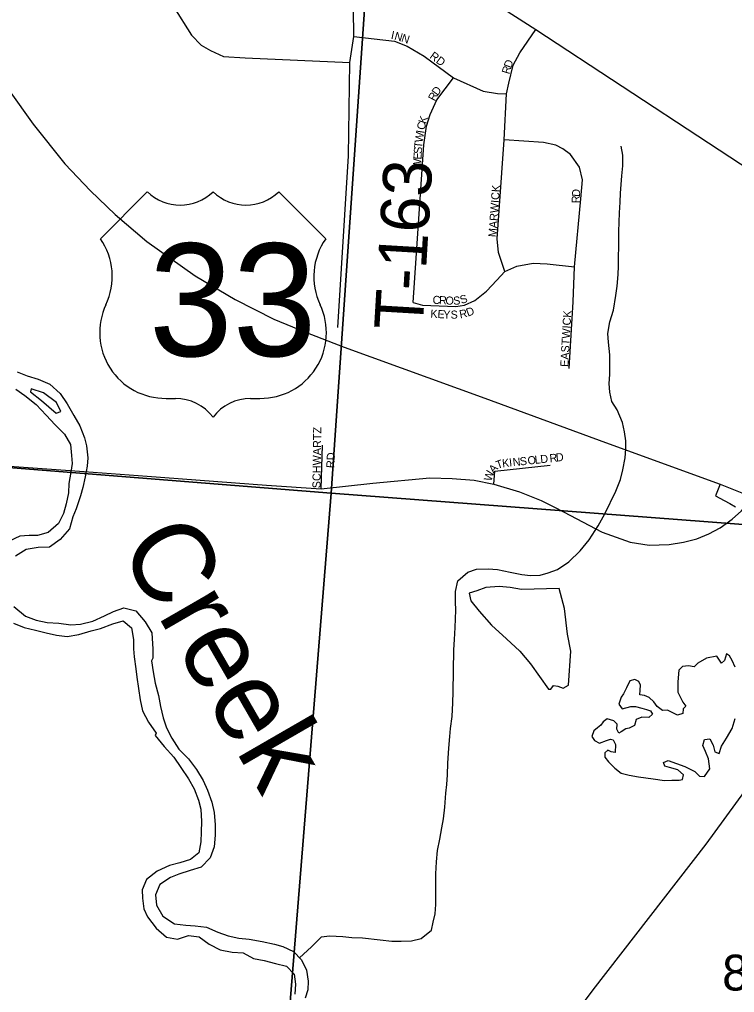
# Model space of a CAD drawing. Extents: x 0 to 34, y 0 to 22.
# Drawn here: x 4.758 to 5.595, y 16.625 to 17.763 of the extents above; entities that cross this region are included whole.
import ezdxf

# ---------------------------------------------------------------- set-up
doc = ezdxf.new("R2010")
doc.units = 0
for name, color, linetype in [('GM_X_City_Street', 7, 'Continuous'), ('GM_X_City_Street_Text', 7, 'Continuous'), ('GM_X_County_Road', 7, 'Continuous'), ('GM_X_Interchange_Ramps', 7, 'Continuous'), ('GM_X_Interstate_Route', 7, 'Continuous'), ('GM_X_Major_River', 7, 'Continuous'), ('GM_X_Major_River_Text', 7, 'Continuous'), ('GM_X_Minor_Lake', 7, 'Continuous'), ('GM_X_Minor_River', 7, 'Continuous'), ('GM_X_Section', 7, 'Continuous'), ('GM_X_Section_Text', 7, 'Continuous'), ('GM_X_Township_Road', 7, 'Continuous'), ('GM_X_Township_Road_Text', 7, 'Continuous'), ('GM_X_Township_Subdivision', 7, 'Continuous'), ('GM_X_Township_Subdivision_Text', 7, 'Continuous'), ('GM_X_US_Location', 7, 'Continuous'), ('GM_X_US_Route', 7, 'Continuous'), ('GM_X_US_Shield', 7, 'Continuous')]:
    doc.layers.add(name, color=color, linetype=linetype)

msp = doc.modelspace()

# ---------------------------------------------------------------- linework, layer by layer
at = {"layer": 'GM_X_City_Street'}
for points in [[(4.8031, 17.8552), (4.8596, 17.8527), (4.8838, 17.8507), (4.8933, 17.8454), (4.906, 17.8276), (4.9148, 17.8153), (4.9389, 17.7773), (4.9593, 17.7446), (4.9706, 17.7328), (4.9816, 17.7267), (4.9967, 17.7194), (5.0224, 17.7178), (5.1448, 17.7126)], [(5.1112, 17.2137), (5.1127, 17.2649)], [(4.5988, 17.2527), (4.5987, 17.2509), (4.8338, 17.234), (4.9075, 17.2287), (5.0472, 17.218), (5.1112, 17.2137), (5.1718, 17.2206), (5.2384, 17.2265), (5.2646, 17.2259), (5.2903, 17.2238), (5.3134, 17.2192), (5.3431, 17.2104), (5.3688, 17.2001), (5.3842, 17.1924), (5.3949, 17.1868), (5.44, 17.1631), (5.4728, 17.1515), (5.4951, 17.1479), (5.5183, 17.1487), (5.5352, 17.1515), (5.5507, 17.1555), (5.565, 17.1611), (5.578, 17.1683), (5.5851, 17.1734)], [(5.3134, 17.2192), (5.3146, 17.2344), (5.3792, 17.2413)], [(5.5851, 17.1734), (5.5923, 17.1785), (5.603, 17.1882), (5.6115, 17.1981), (5.6165, 17.2048), (5.6259, 17.2193), (5.6277, 17.2232), (5.6289, 17.226)]]:
    msp.add_lwpolyline(points, dxfattribs=at)
at = {"layer": 'GM_X_County_Road'}
msp.add_lwpolyline([(5.1496, 17.8918), (5.1573, 17.8838), (5.1678, 17.876), (5.3625, 17.7509), (5.6653, 17.5523), (5.7694, 17.4837), (5.8147, 17.4543), (5.8758, 17.4145), (5.8966, 17.4004), (5.9787, 17.3454), (5.9879, 17.3394), (6.1472, 17.2345), (6.3013, 17.1331), (6.3963, 17.0731), (6.4389, 17.0483), (6.4571, 17.0376), (6.4744, 17.0295), (6.5397, 17.0026), (6.5904, 16.9823)], dxfattribs=at)
at = {"layer": 'GM_X_Interchange_Ramps'}
msp.add_lwpolyline([(5.578, 17.2191), (5.5726, 17.2058), (5.5828, 17.2003), (5.5894, 17.1965), (5.596, 17.1926)], dxfattribs=at)
at = {"layer": 'GM_X_Interstate_Route'}
msp.add_lwpolyline([(5.6064, 16.86), (5.5612, 16.7983), (5.4292, 16.6277), (5.3235, 16.4867), (5.1841, 16.3077), (5.0901, 16.1822)], dxfattribs=at)
at = {"layer": 'GM_X_Major_River'}
for points in [[(4.7554, 17.3506), (4.7671, 17.346), (4.78, 17.3419), (4.7936, 17.3362), (4.8057, 17.3252), (4.8141, 17.3134), (4.8216, 17.2994), (4.8288, 17.2873), (4.8341, 17.2736), (4.8364, 17.2641), (4.8383, 17.2501), (4.8375, 17.2403), (4.8352, 17.2277), (4.8322, 17.2152), (4.8296, 17.2057), (4.8243, 17.1906), (4.8205, 17.1811), (4.8167, 17.167), (4.8057, 17.1545), (4.7932, 17.1454), (4.7799, 17.145), (4.7659, 17.1428), (4.7534, 17.1352)], [(4.7539, 17.3305), (4.7645, 17.3229), (4.7777, 17.3123), (4.7894, 17.2998), (4.8, 17.2888), (4.811, 17.2778), (4.8178, 17.2657), (4.819, 17.2528), (4.8197, 17.2433), (4.8182, 17.2334), (4.8159, 17.2201), (4.8155, 17.2091), (4.8129, 17.1962), (4.8095, 17.1849), (4.8038, 17.1731), (4.7917, 17.1629), (4.7792, 17.1594), (4.7693, 17.1594), (4.7587, 17.1583), (4.7462, 17.1526)], [(4.8065, 17.3043), (4.8016, 17.3146), (4.7864, 17.3259), (4.772, 17.3309), (4.7709, 17.3271)], [(4.7709, 17.3271), (4.7841, 17.3172), (4.8012, 17.3024), (4.8065, 17.3043)], [(4.7515, 17.076), (4.7652, 17.065), (4.7777, 17.0601), (4.7905, 17.0574), (4.8042, 17.0567), (4.8182, 17.0548), (4.8295, 17.0556), (4.8439, 17.059), (4.8575, 17.0654), (4.8682, 17.0704), (4.8803, 17.0745), (4.8943, 17.0711), (4.9053, 17.0583), (4.9132, 17.0454), (4.914, 17.0264), (4.914, 17.0158)], [(4.7511, 17.0567), (4.7636, 17.0517), (4.7769, 17.0483), (4.7894, 17.0453), (4.8015, 17.0427), (4.814, 17.0411), (4.8276, 17.0434), (4.842, 17.0476), (4.853, 17.0506), (4.8674, 17.056), (4.8795, 17.0594), (4.8894, 17.0514), (4.8916, 17.0374), (4.8916, 17.0268), (4.8924, 17.0173), (4.8943, 17.0033), (4.8954, 16.9934), (4.8992, 16.9669), (4.9022, 16.954), (4.909, 16.9407), (4.9181, 16.9282)], [(4.914, 17.0158), (4.9128, 17.0128), (4.9147, 16.9999), (4.917, 16.9866), (4.9208, 16.9722), (4.923, 16.9593), (4.9264, 16.946), (4.9302, 16.9343), (4.9363, 16.9221), (4.9446, 16.9092), (4.956, 16.8979), (4.9654, 16.8854), (4.973, 16.8725), (4.9783, 16.8615), (4.9832, 16.8474), (4.9859, 16.8353), (4.987, 16.8209), (4.987, 16.8088), (4.9859, 16.7951), (4.9813, 16.7822), (4.9707, 16.7712), (4.9578, 16.7674), (4.9446, 16.7632), (4.9347, 16.7591), (4.9222, 16.7511), (4.9173, 16.7389), (4.9184, 16.7268), (4.926, 16.7139), (4.9396, 16.7048), (4.9529, 16.7033), (4.9639, 16.7026), (4.9771, 16.7011), (4.9904, 16.6954), (5.0025, 16.6908), (5.015, 16.6882), (5.0271, 16.6871), (5.0423, 16.6844), (5.0566, 16.6814), (5.0665, 16.6784), (5.079, 16.6727), (5.0881, 16.6628), (5.0941, 16.6507), (5.096, 16.6378), (5.0956, 16.6276), (5.0926, 16.6181)], [(4.9181, 16.9282), (4.917, 16.9252), (4.9276, 16.9123), (4.9389, 16.9001), (4.9469, 16.888), (4.956, 16.8747), (4.9624, 16.863), (4.9677, 16.8497), (4.9703, 16.8391), (4.9711, 16.8247), (4.9707, 16.8125), (4.9703, 16.8008), (4.9681, 16.7879), (4.9582, 16.7803), (4.9457, 16.7765), (4.9336, 16.7731), (4.9192, 16.7666), (4.9067, 16.7568), (4.9018, 16.7446), (4.9022, 16.7351), (4.9037, 16.7226), (4.9078, 16.7132), (4.9181, 16.6999), (4.9302, 16.6893), (4.943, 16.687), (4.9559, 16.6912), (4.9684, 16.6897), (4.9802, 16.6813), (4.993, 16.6745), (5.007, 16.6719), (5.0199, 16.6711), (5.032, 16.6643), (5.0445, 16.662), (5.0578, 16.6586), (5.0706, 16.6556), (5.0794, 16.6461), (5.0812, 16.6344), (5.0805, 16.6226)]]:
    msp.add_lwpolyline(points, dxfattribs=at)
at = {"layer": 'GM_X_Minor_Lake'}
for points in [[(5.3771, 16.9793), (5.3798, 16.9793), (5.3829, 16.9838), (5.3882, 16.983), (5.3942, 16.9807), (5.4007, 16.9841), (5.4033, 17.0239), (5.3993, 17.044), (5.3958, 17.0737), (5.3896, 17.0972), (5.3457, 17.0961), (5.3325, 17.0985), (5.3196, 17.0997), (5.3037, 17.0983), (5.2934, 17.0946), (5.2843, 17.0916), (5.2865, 17.0829), (5.2959, 17.0707), (5.3105, 17.0542), (5.3281, 17.0382), (5.3435, 17.024), (5.3562, 17.0091)], [(5.5955, 17.0052), (5.5922, 17.0132), (5.5892, 17.0186), (5.5854, 17.0209), (5.5831, 17.0129), (5.5796, 17.0099), (5.5744, 17.0179), (5.5623, 17.0158), (5.552, 17.0098), (5.5478, 17.0056), (5.541, 17.0068), (5.5342, 17.0061), (5.5296, 17.0016), (5.5287, 16.988), (5.5286, 16.9758), (5.5345, 16.9644), (5.5379, 16.9594), (5.5348, 16.9564), (5.5344, 16.9511), (5.5283, 16.9489), (5.5166, 16.955), (5.5106, 16.9547), (5.5042, 16.9593), (5.5004, 16.9647), (5.4952, 16.9696), (5.4895, 16.972), (5.4842, 16.9728), (5.4843, 16.9785), (5.4847, 16.9841), (5.4829, 16.9883), (5.4784, 16.9906), (5.4723, 16.9892), (5.4684, 16.9809), (5.4649, 16.9741), (5.4623, 16.9703), (5.4595, 16.962), (5.4633, 16.9566), (5.4735, 16.9592), (5.4792, 16.9591), (5.4864, 16.9572), (5.492, 16.9556), (5.4966, 16.9541), (5.4988, 16.9503), (5.4946, 16.9465), (5.4866, 16.9469), (5.4798, 16.944), (5.4778, 16.9368), (5.4718, 16.9338), (5.4676, 16.9331), (5.4622, 16.9297), (5.4596, 16.9282), (5.457, 16.9328), (5.4574, 16.9385), (5.4537, 16.9423), (5.4499, 16.9438), (5.4457, 16.9446), (5.4412, 16.9412), (5.4385, 16.9375), (5.4346, 16.9341), (5.4301, 16.9307), (5.4281, 16.9243), (5.4311, 16.9193)], [(5.3562, 17.0091), (5.3771, 16.9793)], [(5.455, 16.8872), (5.4622, 16.8811), (5.4716, 16.8788), (5.4826, 16.8768), (5.4996, 16.8747), (5.5128, 16.8727), (5.5215, 16.873), (5.5302, 16.873), (5.534, 16.8737), (5.5352, 16.8794), (5.5285, 16.8851), (5.519, 16.8879), (5.5134, 16.8894), (5.5119, 16.8936), (5.5172, 16.8962), (5.5368, 16.8892), (5.5485, 16.8831), (5.5538, 16.8777), (5.5598, 16.8773), (5.566, 16.8863), (5.5646, 16.8981), (5.5609, 16.9065), (5.5579, 16.9137), (5.5598, 16.9205), (5.5659, 16.9212), (5.57, 16.914), (5.5718, 16.906), (5.5771, 16.9041), (5.5795, 16.9128), (5.5856, 16.9222), (5.5922, 16.9336), (5.5957, 16.9453)], [(5.4311, 16.9193), (5.4368, 16.9162), (5.4451, 16.9196), (5.4497, 16.9211), (5.4527, 16.9203), (5.4557, 16.9149), (5.4552, 16.9055), (5.4507, 16.9063), (5.4465, 16.9082), (5.4431, 16.9052), (5.443, 16.8999), (5.4476, 16.8944)], [(5.4476, 16.8944), (5.455, 16.8872)]]:
    msp.add_lwpolyline(points, dxfattribs=at)
at = {"layer": 'GM_X_Minor_River'}
msp.add_lwpolyline([(5.086, 16.6651), (5.0998, 16.678), (5.1116, 16.6897), (5.1211, 16.6911), (5.1366, 16.6902), (5.1472, 16.689), (5.1597, 16.6885), (5.1801, 16.6861), (5.1937, 16.6848), (5.2047, 16.6848), (5.2168, 16.685), (5.2282, 16.688), (5.2404, 16.6974), (5.2424, 16.7068), (5.2444, 16.7167), (5.2453, 16.7277), (5.2455, 16.752), (5.2452, 16.7634), (5.2461, 16.7774), (5.2474, 16.7907), (5.2502, 16.8039), (5.2525, 16.8172), (5.2545, 16.8278), (5.2558, 16.8414), (5.2571, 16.8577), (5.2583, 16.868), (5.2592, 16.8794), (5.2593, 16.893), (5.2606, 16.9105), (5.2619, 16.9241), (5.2627, 16.9336), (5.2644, 16.9476), (5.2653, 16.9635), (5.2658, 16.9764), (5.2663, 17.0254), (5.2671, 17.0375), (5.268, 17.0516), (5.2685, 17.0618), (5.2686, 17.0717), (5.2683, 17.0815), (5.2684, 17.0937), (5.2712, 17.1062), (5.2827, 17.1163), (5.2929, 17.1197), (5.3065, 17.1203), (5.3175, 17.1195), (5.3323, 17.1163), (5.3462, 17.1135), (5.3561, 17.1123), (5.3674, 17.113), (5.3769, 17.1156), (5.3879, 17.1196), (5.4009, 17.1283), (5.4143, 17.1414), (5.425, 17.1542), (5.4354, 17.1705), (5.4431, 17.1845), (5.4562, 17.2109), (5.4616, 17.2249), (5.4644, 17.2359), (5.4668, 17.2499), (5.4677, 17.2605), (5.4678, 17.27), (5.4663, 17.2806), (5.4638, 17.2913), (5.4575, 17.3061), (5.4515, 17.3161), (5.449, 17.3267), (5.4483, 17.337), (5.4488, 17.3476), (5.449, 17.3707), (5.4476, 17.3855), (5.4466, 17.3954), (5.449, 17.409), (5.4533, 17.4227), (5.4561, 17.4401), (5.4577, 17.4507), (5.4586, 17.4644), (5.4591, 17.4742), (5.4592, 17.4852), (5.4597, 17.497), (5.4595, 17.5148), (5.46, 17.5258), (5.4604, 17.5368), (5.4609, 17.549), (5.4614, 17.5596), (5.4631, 17.5801), (5.4644, 17.5918), (5.4641, 17.604), (5.4623, 17.6146)], dxfattribs=at)
at = {"layer": 'GM_X_Section'}
for points in [[(4.2418, 18.2267), (4.7469, 18.1907), (5.1885, 18.1592), (5.123, 17.2087), (4.1767, 17.2841)], [(5.1885, 18.1592), (5.2507, 18.1559), (5.7484, 18.1169), (6.2087, 18.0808), (6.1439, 17.131), (5.123, 17.2087)], [(4.1767, 17.2841), (5.123, 17.2087), (5.0408, 16.1927), (4.1066, 16.2613), (4.1718, 17.2163)], [(5.123, 17.2087), (6.1439, 17.131), (6.0779, 16.1089), (5.0408, 16.1927)]]:
    msp.add_lwpolyline(points, close=True, dxfattribs=at)
at = {"layer": 'GM_X_Township_Road'}
msp.add_lwpolyline([(5.1307, 17.4024), (5.1431, 17.6035), (5.1448, 17.7126), (5.1493, 17.7429), (5.149, 17.7754), (5.16, 17.8569), (5.1604, 17.8633), (5.1609, 17.8655), (5.1617, 17.8686), (5.1678, 17.876)], dxfattribs=at)
at = {"layer": 'GM_X_Township_Subdivision'}
for points in [[(5.326, 17.4681), (5.3188, 17.4901), (5.3172, 17.5063), (5.3254, 17.6222), (5.3282, 17.6757), (5.3307, 17.6884), (5.336, 17.7092), (5.3438, 17.7239), (5.3625, 17.7509)], [(5.1493, 17.7429), (5.197, 17.7376), (5.2118, 17.7315), (5.2318, 17.7198), (5.2659, 17.6944), (5.3007, 17.6789), (5.3177, 17.6763), (5.3282, 17.6757)], [(5.219, 17.4318), (5.2314, 17.6161), (5.2345, 17.638), (5.2386, 17.6517), (5.2466, 17.6687), (5.2659, 17.6944)], [(5.4013, 17.3546), (5.4062, 17.4325), (5.4077, 17.4734), (5.4152, 17.5532), (5.4172, 17.5753), (5.4136, 17.59), (5.4029, 17.6047), (5.394, 17.6116), (5.3858, 17.6157), (5.3715, 17.619), (5.3254, 17.6222)], [(5.219, 17.4318), (5.2299, 17.4287), (5.2689, 17.4272), (5.2791, 17.4287), (5.2912, 17.434), (5.3045, 17.445), (5.3166, 17.4579), (5.326, 17.4681), (5.34, 17.4742), (5.3593, 17.4779), (5.3756, 17.4768), (5.4077, 17.4734)]]:
    msp.add_lwpolyline(points, dxfattribs=at)
at = {"layer": 'GM_X_US_Route'}
msp.add_lwpolyline([(4.6943, 17.7748), (4.7113, 17.7399), (4.7276, 17.7105), (4.7461, 17.6796), (4.7741, 17.6405), (4.8111, 17.5941), (4.8412, 17.5624), (4.8703, 17.5346), (4.9071, 17.5032), (4.9636, 17.4629), (5.0105, 17.4353), (5.0559, 17.4124), (5.093, 17.397), (5.1381, 17.3797), (5.3028, 17.3197), (5.444, 17.2679), (5.578, 17.2191), (5.6056, 17.2084)], dxfattribs=at)
at = {"layer": 'GM_X_US_Shield'}
for p, q in [((4.9077, 17.5613), (4.8528, 17.5063)), ((5.1165, 17.5063), (5.0616, 17.5613)), ((4.9297, 17.3196), (4.9407, 17.3196)), ((5.0286, 17.3196), (5.0396, 17.3196))]:
    msp.add_line(p, q, dxfattribs=at)
for centre, radius, start, end in [((4.9462, 17.6005), 0.0549, 225.573, 314.427), ((5.0231, 17.6005), 0.0549, 225.573, 314.427), ((4.7898, 17.4622), 0.0769, 334.5471, 35.0009), ((5.1795, 17.4622), 0.0769, 144.9991, 205.4529), ((4.9289, 17.3965), 0.0769, 154.8319, 270.6383), ((5.0404, 17.3965), 0.0769, 269.3617, 25.1681), ((4.9407, 17.2646), 0.0549, 36.8699, 90), ((5.0286, 17.2646), 0.0549, 90, 143.1301)]:
    msp.add_arc(centre, radius, start, end, dxfattribs=at)

# ---------------------------------------------------------------- texts
at = {"layer": 'GM_X_City_Street_Text'}
for s, rotation, p in [('SCHWARTZ', 89.2466, (5.1104, 17.2144)), ('RD', 86.989, (5.1265, 17.2378)), ('D', 6.0967, (5.3863, 17.2456)), ('T', 19.4848, (5.3176, 17.2368)), ('K', 6.0967, (5.3234, 17.2389)), ('I', 6.0967, (5.3316, 17.2398)), ('N', 6.0967, (5.3358, 17.2402)), ('S', 6.0967, (5.3441, 17.2411)), ('O', 6.0967, (5.3532, 17.2421)), ('L', 6.0967, (5.3615, 17.2429)), ('D', 6.0967, (5.3681, 17.2437)), ('R', 6.0967, (5.3789, 17.2448)), ('W', 73.0372, (5.3103, 17.222)), ('A', 46.261, (5.3129, 17.2314))]:
    msp.add_text(s, height=0.00947, rotation=rotation, dxfattribs=at).set_placement(p)
at = {"layer": 'GM_X_Major_River_Text'}
msp.add_text('Creek', height=0.09469, rotation=300.0021, dxfattribs=at).set_placement((4.8734, 17.1455))
at = {"layer": 'GM_X_Section_Text'}
msp.add_text('8', height=0.0419, rotation=0, dxfattribs=at).set_placement((5.5805, 16.627))
at = {"layer": 'GM_X_Township_Road_Text'}
msp.add_text('T-163', height=0.05682, rotation=86.6332, dxfattribs=at).set_placement((5.2298, 17.3986))
at = {"layer": 'GM_X_Township_Subdivision_Text'}
for s, rotation, p in [('I', 348.3815, (5.1923, 17.7403)), ('N', 343.8054, (5.1962, 17.7395)), ('N', 341.724, (5.2042, 17.7372)), ('RD', 323.7411, (5.2374, 17.7183)), ('D', 70.1065, (5.3334, 17.7052)), ('R', 73.424, (5.3313, 17.6982)), ('R', 63.2177, (5.2443, 17.6666)), ('D', 54.3454, (5.2474, 17.673)), ('C', 77.7424, (5.2322, 17.633)), ('K', 72.277, (5.2337, 17.6401)), ('W', 81.4609, (5.2299, 17.6184)), ('I', 81.0478, (5.2315, 17.6291)), ('T', 84.5014, (5.2293, 17.6119)), ('S', 86.5822, (5.2289, 17.6053)), ('W', 86.5852, (5.2279, 17.5878)), ('E', 86.5822, (5.2285, 17.5987)), ('MARWICK', 85.8543, (5.3162, 17.5079)), ('D', 86.0405, (5.4139, 17.5551)), ('R', 88.6158, (5.4137, 17.5477)), ('C', 356.8902, (5.2414, 17.4303)), ('R', 356.9149, (5.2489, 17.4299)), ('O', 356.8953, (5.2564, 17.4295)), ('S', 2.5405, (5.2658, 17.4291)), ('S', 19.1166, (5.2754, 17.4299)), ('D', 20.8727, (5.2829, 17.4151)), ('K', 356.7414, (5.2388, 17.4141)), ('E', 356.7721, (5.2471, 17.4136)), ('Y', 357.5158, (5.2539, 17.4132)), ('S', 359.4177, (5.2626, 17.4129)), ('R', 11.5173, (5.2739, 17.4131)), ('EASTWICK', 86.819, (5.4004, 17.3562))]:
    msp.add_text(s, height=0.00947, rotation=rotation, dxfattribs=at).set_placement(p)
at = {"layer": 'GM_X_US_Location'}
for s in ['0', '/']:
    msp.add_text(s, height=0.000189, dxfattribs=at).set_placement((4.9846, 17.4339))
msp.add_text('33', height=0.000189, rotation=0, dxfattribs=at).set_placement((4.9455, 17.3947))
at = {"layer": 'GM_X_US_Shield'}
msp.add_text('33', height=0.13184, dxfattribs=at).set_placement((4.9096, 17.369))

doc.saveas('drawing.dxf')
